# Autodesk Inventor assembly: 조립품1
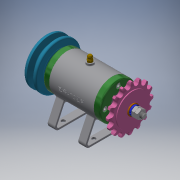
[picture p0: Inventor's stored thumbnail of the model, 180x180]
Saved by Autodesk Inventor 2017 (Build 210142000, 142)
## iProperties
Part Number: 조립품1
Material: 일반
Document SubType Name: Assembly
Designer: Administrator
Author: Administrator
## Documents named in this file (16)
- C:\Users\Administrator\Desktop\711206V1035\조립품1.iam
- C:\Users\Administrator\Desktop\711206V1035\본체.ipt
- C:\Users\Administrator\Desktop\711206V1035\축.ipt
- C:\Users\Administrator\Desktop\711206V1035\커버.ipt
- C:\Users\Administrator\Desktop\711206V1035\베어링 6002.ipt
- C:\Users\Administrator\Desktop\711206V1035\오일 실 15 x 25 x 7.ipt
- C:\Users\Administrator\Desktop\711206V1035\볼트 M4 x 12.ipt
- C:\Users\Administrator\Desktop\711206V1035\키 3 x 3.ipt
- C:\Users\Administrator\Desktop\711206V1035\V벨트풀리.ipt
- C:\Users\Administrator\Desktop\711206V1035\스프로킷.ipt
- C:\Users\Administrator\Desktop\711206V1035\너트 M8.ipt
- C:\Users\Administrator\Desktop\711206V1035\와셔 8 x 17.ipt
- C:\Users\Administrator\Desktop\711206V1035\스프링와셔 8.ipt
- C:\Users\Administrator\Desktop\711206V1035\니플 M6 x 0.75.ipt
- C:\Users\Administrator\Desktop\711206V1035\와셔 6 x 11.5.ipt
- C:\Users\Administrator\Desktop\711206V1035\볼트 M6 x 8.ipt
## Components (11 placed, 3 different names)
1. KS B 2023 6002 - 15 x 32 x 9:1
2. KS B 2023 6002 - 15 x 32 x 9:2
3. V벨트풀리:1
4. ISO 4762 M4 x 12:1
5. ISO 4762 M4 x 12:3
6. ISO 4762 M4 x 12:4
7. ISO 4762 M4 x 12:5
8. ISO 4762 M4 x 12:2
9. ISO 4762 M4 x 12:6
10. ISO 4762 M4 x 12:7
11. ISO 4762 M4 x 12:8
